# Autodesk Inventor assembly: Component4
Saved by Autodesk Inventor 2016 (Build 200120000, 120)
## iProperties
Created: 2018-05
Part Number: Component4
Document SubType Name: Assembly
Designer: Administrator
Title: Component4
Author: Administrator
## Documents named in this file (2)
- c:\worker\convert-fusion-mar-2018\tmp\job-1\16\output\files\8c58ff39-88bb-4352-afd9-60265520bae5\Component4_1.iam
- c:\worker\convert-fusion-mar-2018\tmp\job-1\16\output\files\8c58ff39-88bb-4352-afd9-60265520bae5\Component5.ipt
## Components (1 placed, 1 different names)
1. Component5:1
